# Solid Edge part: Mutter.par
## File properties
Sűrűség: 0,000 kg/m^3
Pontosság: 0,990
Author: bmolnar
Last saved by: psaghy
Revision: 77
Username: bmolnar
Dokumentum tartalom típus: 0
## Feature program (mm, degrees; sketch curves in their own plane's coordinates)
base feature "unnamed BaseFeature 1"
sketch for "Furat_1" plane through (9, 0, 0) normal (1, 0, 0) x-axis (0, 1, 0)
hole "Furat_1" through  StartChamferOffset = 0.47 mm; StartChamferAngle = 45 deg
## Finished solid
Body 1: solid body, 23 faces, 47 edges, 26 vertices.
  Faces by surface: cone 14, plane 8, cylinder 1
  Edges by curve: spline 24, circle 16, line 7
Bounding box of the edges (mm): 9.000 x 34.641 x 30.000, from (0, -17.3205, -15) to (9, 17.3205, 15).
Cylindrical faces by radius (mm): R9.188 x1
Conical faces (half-angle, radius in mm at the cone's reference point): 45 deg R9.658 x1, 60 deg R9.5939 x1, 60 deg R16.1603 x12
Planar faces by outward normal: +x 1, +z 1, -x 1, -z 1, oblique 4
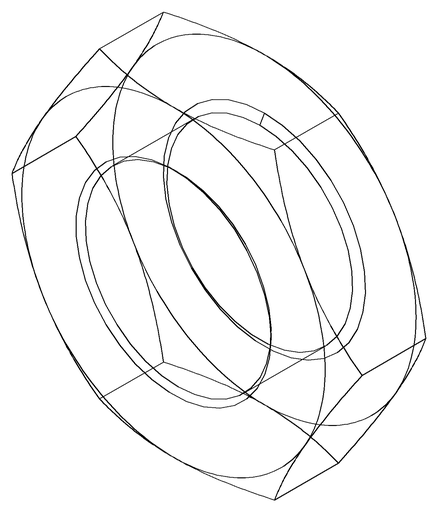
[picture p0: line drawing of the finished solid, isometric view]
